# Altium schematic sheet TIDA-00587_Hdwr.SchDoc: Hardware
size 431 x 279 mm; Date: Not shown in title block; ApprovedBy: Not shown in title block; CheckedBy: Not shown in title block; Author: Not shown in title block; CompanyName: Not shown in title block; DrawnBy: Gordon Varney; Engineer: Gordon Varney; Organization: BMS; Address1: Not shown in title block; Address2: Not shown in title block; Address3: Not shown in title block; Address4: Not shown in title block; DocumentNumber: 1; Revision: Use project parameter SCH_Rev; SheetNumber: 2; SheetTotal: 2; PageSetup: Record=PageOptions¦CenterHorizontal=True¦CenterVertical=True¦PrintScale=1.00¦XCorrection=1.00¦YCorrection=1.00¦PrintKind=0¦BorderSize=5000000¦LeftOffset=0¦BottomOffset=0¦Orientation=2¦PaperLength=1000¦PaperWidth=1000¦Scale=100¦PaperSource=15¦PrintQuality=600¦MediaType=1¦DitherType=10¦PaperKind=Letter¦PrintScaleMode=1
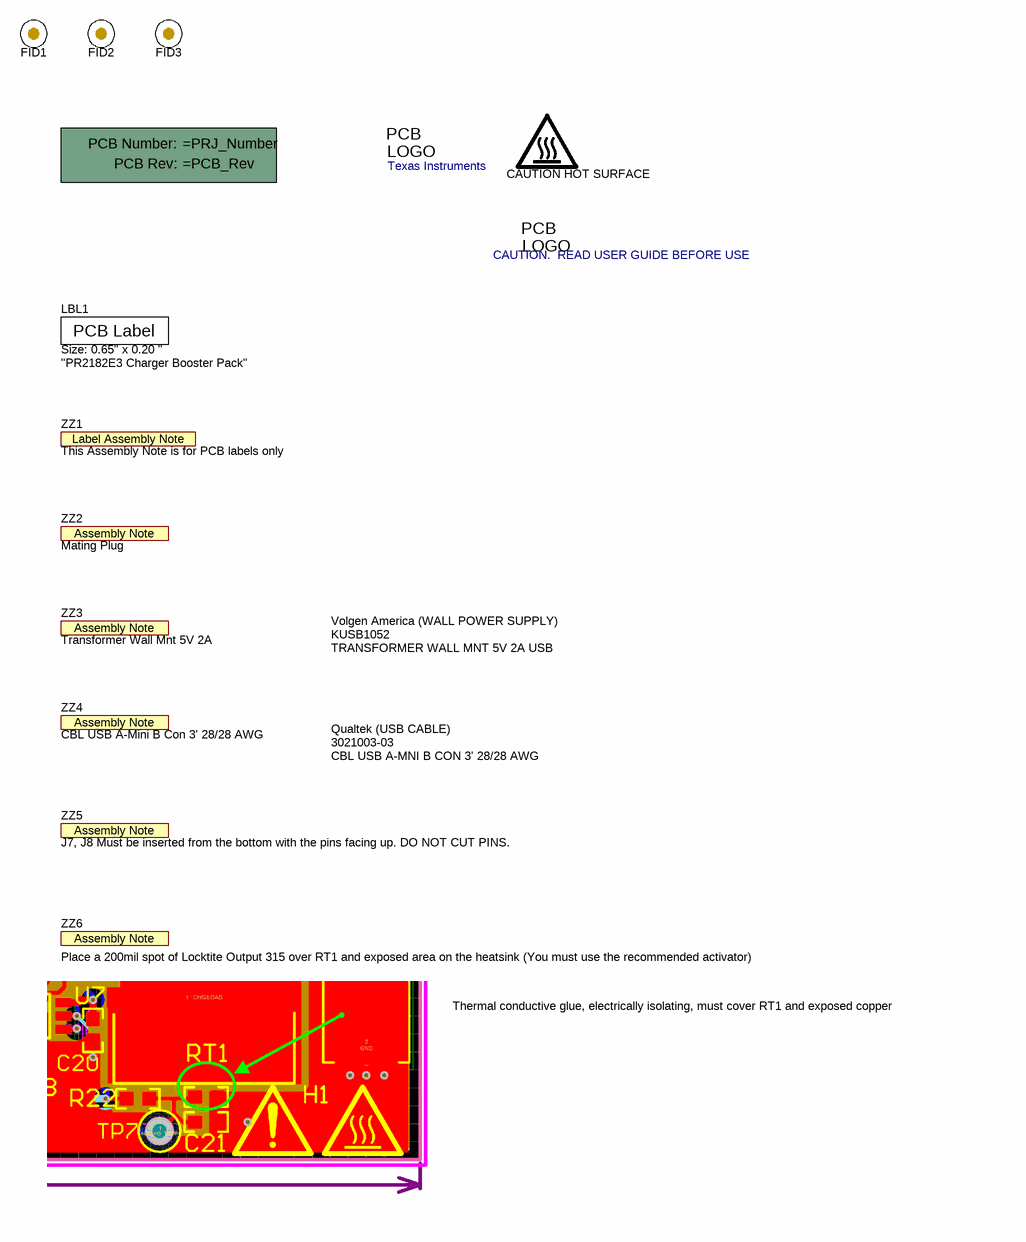
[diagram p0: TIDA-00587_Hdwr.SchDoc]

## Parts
!PCB1  Printed Circuit Board  (value not drawn)  (mechanical)
FID1  Fiducial  [Fiducial10-20]  (value not drawn)
FID2  Fiducial  [Fiducial10-20]  (value not drawn)
FID3  Fiducial  [Fiducial10-20]  (value not drawn)
LBL1  Size: 0.65" x 0.20 "  value "PR2182E3 Charger Booster Pack"  [Label_650x200]
Logo1  Texas Instruments  [TI_Stacked_Overlay_Medium]  (no BOM)
Logo2  CAUTION HOT SURFACE  [IEC_HotSurface_Small]  (no BOM)
Logo3  CAUTION.  READ USER GUIDE BEFORE USE  [IEC_Caution_Small]  (no BOM)
ZZ1  This Assembly Note is for PCB labels only  [AssemblyNoteLabel]  (no BOM)
ZZ2  Mating Plug  [AssemblyNote]
ZZ3  Transformer Wall Mnt 5V 2A  [AssemblyNote]
ZZ4  CBL USB A-Mini B Con 3' 28/28 AWG  [AssemblyNote]
ZZ5  J7, J8 Must be inserted from the bottom with the pins facing up. DO NOT CUT PINS.  [AssemblyNote]  (no BOM)
ZZ6  Place a 200mil spot of Locktite Output 315 over RT1 and exposed area on the heatsink (You must use the recommended activator)  [AssemblyNote]  (no BOM)

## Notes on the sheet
- Volgen America (WALL POWER SUPPLY)
- KUSB1052
- TRANSFORMER WALL MNT 5V 2A USB
- Qualtek (USB CABLE)
- 3021003-03
- CBL USB A-MNI B CON 3' 28/28 AWG
- Thermal conductive glue, electrically isolating, must cover RT1 and exposed copper

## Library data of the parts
!PCB1 = PCB: Manufacturer: Any; SymbolCreator: a0412235
FID1-FID3 = Fiducial: Fiducial mark.  There is nothing to buy or mount.; SymbolCreator: codlsc
LBL1 = THT-14-423-10: Thermal Transfer Printable Labels, 0.650" W x 0.200" H - 10,000 per roll; Manufacturer: Brady; SymbolCreator: a0412235; CompType: Label
Logo1 = TI_Logo: Texas Instrument Corporate Signature; SymbolCreator: a0412235
Logo2 = IEC_HotSurface: IEC 61010-1 Hot Surface Warning; SymbolCreator: a0412235
Logo3 = IEC_Caution: IEC 61010-1 Caution Warning; SymbolCreator: a0412235
ZZ1 = AssemblyNoteLabel: SymbolCreator: a0412235
ZZ2 = AssemblyNote: This is the mating Plug for Connector J3; Manufacturer: On-Shore Technology; PartNumber: OSTTJ0311530; SymbolCreator: codlsc
ZZ3 = AssemblyNote: Manufacturer: Volgen America; PartNumber: KUSB1052; SymbolCreator: codlsc; Value: 5V 2A
ZZ4 = AssemblyNote: Manufacturer: Qualtek; PartNumber: 3021003-03; SymbolCreator: codlsc
ZZ5 = AssemblyNote: Manufacturer: On-Shore Technology; PartNumber: OSTTJ0311530; SymbolCreator: codlsc; Value: Plug
ZZ6 = AssemblyNote: Place a 200mil spot of Locktite Output 315 over RT1 and exposed area on the copper of the heatsink (You must use the recommended activator to get proper cure); Manufacturer: On-Shore Technology; PartNumber: OSTTJ0311530; SymbolCreator: codlsc; Value: Plug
